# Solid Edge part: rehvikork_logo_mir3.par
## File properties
Author: KULL
Template: Iso Metric Part.par
Last saved by: KULL
Revision: 2
Application: Solid Edge
Accuracy: 0,990
Username: KULL
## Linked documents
rehvikork_logo.par
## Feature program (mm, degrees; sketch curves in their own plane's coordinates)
part copy "CopiedPart_1"
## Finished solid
Body 1: solid body, 86 faces, 199 edges, 116 vertices, 2 separate solids.
  Faces by surface: spline 40, blend 36, sphere 8, cone 1, torus 1
  Edges by curve: intersection 112, line 32, circle 29, curve on surface 26
Bounding box of the edges (mm; curved faces can reach further): 1.405 x 13.917 x 13.917, from (-0.4589, -6.9587, -6.9587) to (0.946, 6.9587, 6.9587).
Conical faces (half-angle, radius in mm at the cone's reference point): 11.8765 deg R7 x1
Toroidal faces (ring radius, tube radius in mm): R6.763 r0.2 x1
Spherical faces by radius (mm): R0.2 x4, R33.3132 x2, R34.0132 x2
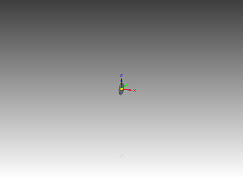
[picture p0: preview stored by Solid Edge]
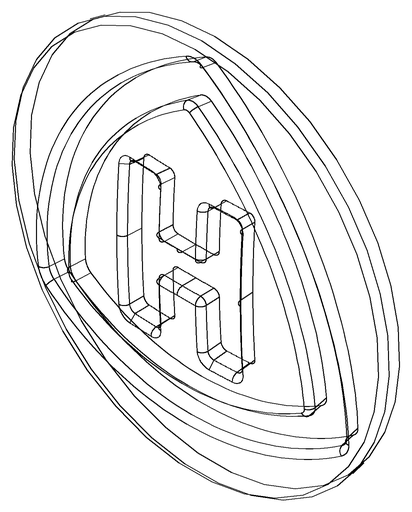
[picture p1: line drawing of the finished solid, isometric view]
